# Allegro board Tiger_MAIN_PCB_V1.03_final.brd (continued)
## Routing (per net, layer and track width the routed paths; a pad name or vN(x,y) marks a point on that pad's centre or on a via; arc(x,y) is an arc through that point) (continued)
M_B_DQS_DN*<5>: length 60.5
  TOP w0.076: U1.AY26 200.58,56.26 200.56,56.24 200.5,56.24 200.37,56.19 200.37,56.19 200.29,56.05 200.24,55.94 200.24,55.66 200.28,55.58 200.28,55.37 200.23,55.26 200.23,55.04 200.28,54.93 200.28,54.64 200.07,54.42 200.07,53.21 199.87,53.01 199.87,48.48 199.38,48 199.18,48 198.95,48.24 v2(198.95,48.33)
  TOP w0.114: CN1.74 221.11,14.92 220.97,15.07 220.97,15.72 221.15,15.9 221.47,15.9 v2(221.62,15.75)
  LAY3 w0.076: v2(198.95,48.33) 199.12,48.15 199.33,48.15 199.57,47.92 199.57,45.5 198.12,44.05 198.12,44.03 198.08,44 198.08,43.99 198.08,43.98 198.08,43.98 198.07,43.98
  LAY3 w0.094: v2(221.62,15.75) 221.81,15.94 222.1,15.94 222.32,16.16 222.32,17.19 220.64,18.87 220.64,20.91 218.68,22.87 212.46,22.87 211.77,23.56 211.77,23.57 211.77,23.57 197.68,37.65 197.68,43.59 198.07,43.98 198.07,43.98
M_B_DQS_DN*<6>: length 56.8
  TOP w0.076: U1.AR25 v2(201.53,58.88)
  TOP w0.114: v2(181.87,19.45) 182,19.59 182.44,19.59 182.72,19.87 182.72,21.85 CN1.219
  LAY6 w0.076: 197.93,51 201.04,54.1 201.04,55.09 202.21,56.27 202.21,56.94 201.91,57.24 201.91,58.5 v2(201.53,58.88)
  LAY6 w0.094: 197.93,51 197.93,46.09 195.49,43.65 188.16,36.32 188.14,36.32 182.89,31.07 182.89,29.91 182.81,29.83 182.26,29.83 182.05,29.62 182.05,29.27 182.26,29.06 182.79,29.06 182.89,28.96 182.89,28.77 182.81,28.69 182.26,28.69 182.05,28.48 182.05,28.13 182.26,27.92 182.79,27.92 182.89,27.81 182.89,27.63 182.81,27.54 182.26,27.54 182.05,27.34 182.05,26.99 182.26,26.78 182.79,26.78 182.89,26.67 182.89,25.85 181.34,24.3 181.34,23.46 181.36,23.44 181.36,22.91 181.14,22.69 181.14,19.82 181.36,19.59 181.72,19.59 v2(181.87,19.45)
M_B_DQS_DN*<7>: length 56.3
  TOP w0.076: U1.AR22 v2(199.7,58.88)
  TOP w0.114: CN1.240 177.61,15.58 v2(177.7,15.67)
  LAY6 w0.076: v2(199.7,58.88) 199.33,58.51 199.33,57.23 199.04,56.94 199.04,55.78 197.62,54.36 197.62,54.21 196.71,53.3 196.12,53.3 193.68,50.86 193.68,48.35 182.95,37.62 182.95,36.99 182.18,36.21 182.18,36.19 182.16,36.18
  LAY6 w0.094: v2(177.7,15.67) 177.46,15.91 177.46,23.41 177.5,23.45 177.5,24.83 177.29,25.04 177.17,25.04 177.07,25.13 177.07,25.32 177.17,25.41 177.29,25.41 177.5,25.62 177.5,25.97 177.29,26.18 177.17,26.18 177.07,26.27 177.07,26.46 177.17,26.55 177.29,26.55 177.5,26.76 177.5,31.51 181.8,35.82 181.8,35.82 182.16,36.18
M_B_DQS_DP<0>: length 59.5
  TOP w0.076: U1.AY38 208.32,56.19 208.4,56.05 208.44,55.94 208.44,55.66 208.41,55.58 208.41,55.37 208.46,55.26 208.46,55.24 208.46,55.07 208.46,55.04 208.41,54.93 208.41,54.54 208.54,54.41 208.54,53.92 208.36,53.74 208.36,52.73 208.53,52.57 208.53,50.17 208.29,49.93 208.03,49.93 207.97,49.87 v2(207.97,49.63)
  TOP w0.114: v2(235.86,20.03) 236.01,19.89 236.35,19.89 236.54,20.07 236.54,20.9 236.37,21.07 CN1.13
  LAY3 w0.094: v2(207.97,49.63) 207.97,49.79 207.82,49.94 207.53,49.94 207.38,49.8 207.38,48.75 207.57,48.56 207.57,46 207.58,45.99 207.61,46.12 207.61,45.96 207.61,45.96 207.61,45.79 207.62,45.78 207.62,45.14 216.16,36.6 223.02,36.6 223.3,36.32 223.32,36.32 224.36,35.28 235.17,24.47 235.17,23.46 235.15,23.44 235.15,23.21 235.25,23.11 235.5,23.11 235.7,22.91 235.7,22.57 235.5,22.37 235.25,22.37 235.15,22.28 235.15,22.09 235.25,21.99 235.47,21.99 235.67,21.79 235.67,21.45 235.47,21.25 235.25,21.25 235.15,21.16 235.15,19.87 235.4,19.63 235.5,19.63 235.6,19.72 235.6,19.97 235.66,20.03 v2(235.86,20.03)
M_B_DQS_DP<1>: length 60.9
  TOP w0.076: v2(204.41,47.68) 204.67,47.94 204.99,47.94 205.3,48.24 205.3,53.72 205.43,53.85 205.43,54.97 205.37,55.08 205.37,55.09 205.37,55.2 205.43,55.33 205.43,55.61 205.39,55.69 205.39,55.91 205.42,55.97 205.47,56.05 205.51,56.07 205.6,56.07 205.66,56.01 205.66,55.8 U1.BA34
  TOP w0.114: v2(230.61,15.75) 230.82,15.96 231.04,15.96 231.26,15.75 231.26,15.06 231.11,14.92 CN1.34
  LAY3 w0.076: 204.36,43.88 204.36,44.9 204.86,45.4 204.86,47.85 204.73,47.98 204.54,47.98 204.41,47.85 v2(204.41,47.68)
  LAY3 w0.094: 204.36,43.88 204.36,42.1 210.18,36.27 210.18,36.25 214.73,31.71 221.93,31.71 229.98,23.65 229.98,23.44 230,23.43 230,19.29 229.75,19.05 229.75,16.19 229.98,15.96 230.4,15.96 v2(230.61,15.75)
M_B_DQS_DP<2>: length 52.8
  TOP w0.076: U1.AR38 v2(208.85,58.88)
  TOP w0.114: v2(192.78,20.19) 192.86,20.28 CN1.179
  LAY6 w0.076: v2(208.85,58.88) 208.83,58.88 208.32,58.37 208.32,57.12 208.35,57.09 208.35,53.98 206.82,52.46 206.82,52.45 206.83,52.44
  LAY6 w0.094: v2(192.78,20.19) 192.78,23.43 192.77,23.44 192.77,24.77 192.98,24.97 193.34,24.97 193.43,25.07 193.43,25.26 193.34,25.35 192.98,25.35 192.77,25.56 192.77,25.91 192.98,26.12 193.34,26.12 193.43,26.21 193.43,26.4 193.34,26.49 192.98,26.49 192.77,26.7 192.77,27.05 192.98,27.26 193.34,27.26 193.43,27.35 193.43,27.54 193.34,27.64 192.98,27.64 192.77,27.85 192.77,28.55 193.39,29.17 193.69,29.17 193.78,29.08 193.91,29.08 194.04,29.21 194.04,29.34 193.95,29.44 193.95,29.73 194.2,29.98 194.5,29.98 194.59,29.89 194.72,29.89 194.85,30.02 194.85,30.15 194.76,30.25 194.76,30.54 195.01,30.79 195.31,30.79 195.4,30.7 195.53,30.7 195.66,30.83 195.66,30.96 195.57,31.06 195.57,31.35 195.82,31.6 196.11,31.6 196.24,31.47 196.34,31.47 196.47,31.6 196.47,31.77 196.38,31.86 196.38,32.16 198.81,34.59 198.81,36.24 206.83,44.26 206.83,52.44
M_B_DQS_DP<3>: length 55
  TOP w0.076: U1.AR32 v2(205.19,58.88)
  TOP w0.114: v2(187.11,15.75) 187.22,15.86 187.24,15.86 187.26,15.88 187.61,15.88 187.75,15.74 187.75,13.93 CN1.200
  LAY6 w0.076: 203.12,46.62 203.12,46.63 203.11,46.64 203.11,46.69 203.1,46.7 203.1,52.45 203.94,53.29 203.94,54.45 205.15,55.65 205.15,56.67 205.74,57.26 205.74,58.48 205.33,58.88 v2(205.19,58.88)
  LAY6 w0.094: 203.12,46.62 203.12,45.08 198.93,40.88 198.38,40.88 193.55,36.06 193.55,36.04 188.72,31.2 188.72,24.98 188.73,24.97 188.73,23.79 188.72,23.78 188.72,23.44 188.71,23.43 188.71,17.12 187.56,15.98 187.34,15.98 v2(187.11,15.75)
M_B_DQS_DP<4>: length 58.8
  TOP w0.076: U1.AY30 203.33,56.19 203.42,56.05 203.46,55.94 203.46,55.66 203.43,55.58 203.43,55.37 203.48,55.26 203.48,55.04 203.43,54.93 203.43,54.32 203.46,54.29 203.46,53.89 203.46,53.89 203.46,53.75 203.09,53.38 203.09,50.26 202.9,50.07 202.82,50.07 202.53,49.78 v2(202.53,49.63)
  TOP w0.114: CN1.55 225.86,21.11 226.11,20.86 226.11,20.03 225.91,19.84 225.56,19.84 v2(225.37,20.03)
  LAY3 w0.076: v2(202.53,49.63) 202.42,49.63 202.28,49.77 202.28,49.96 202.2,50.03 202,50.03 201.88,49.92 201.88,46.16 202.08,45.96 202.08,45.83 202.08,45.26 201.12,44.3 201.12,43.87 201.14,43.85 201.14,43.8 201.15,43.79 201.15,43.78
  LAY3 w0.094: v2(225.37,20.03) 224.96,19.63 224.84,19.63 224.7,19.77 224.7,23.7 224.47,23.93 224.47,23.94 220.19,28.23 214.93,28.23 214.72,28.02 214.72,27.74 214.62,27.65 214.43,27.65 214.34,27.74 214.34,28.02 214.13,28.23 213.78,28.23 213.57,28.02 213.57,27.74 213.48,27.65 213.29,27.65 213.2,27.74 213.2,28.02 212.99,28.23 212.37,28.23 204.29,36.31 204.28,36.31 201.15,39.43 201.15,43.78
M_B_DQS_DP<5>: length 60.5
  TOP w0.076: U1.BA26 200.68,55.8 200.68,56.01 200.61,56.07 200.53,56.07 200.49,56.05 200.44,55.97 200.41,55.91 200.41,55.69 200.45,55.61 200.45,55.33 200.39,55.2 200.39,55.1 200.45,54.96 200.45,54.57 200.23,54.35 200.23,53.15 200.03,52.94 200.03,48.41 199.45,47.84 199.11,47.84 v2(198.95,47.68)
  TOP w0.114: CN1.76 220.62,14.92 220.76,15.07 220.76,15.8 221.06,16.1 221.38,16.1 v2(221.62,16.33)
  LAY3 w0.076: 197.94,44.11 199.4,45.57 199.4,47.85 199.26,47.99 199.07,47.99 198.95,47.87 v2(198.95,47.68)
  LAY3 w0.094: v2(221.62,16.33) 221.82,16.13 222.02,16.13 222.14,16.24 222.14,17.12 220.45,18.8 220.45,20.83 218.6,22.69 212.39,22.69 211.77,23.3 211.75,23.3 211.63,23.43 211.63,23.43 199.03,36.03 199.03,36.05 197.5,37.58 197.5,43.66 197.94,44.11
M_B_DQS_DP<6>: length 56.8
  TOP w0.076: U1.AR27 v2(202.45,58.88)
  TOP w0.114: CN1.221 182.5,21.86 182.5,19.97 182.34,19.81 182.09,19.81 v2(181.87,20.03)
  LAY6 w0.076: v2(202.45,58.88) 202.45,59.05 202.38,59.11 202.15,59.11 202.08,59.04 202.08,57.31 202.38,57 202.38,56.2 201.21,55.03 201.21,54.04 198.12,50.95 198.12,50.94
  LAY6 w0.094: 198.12,50.94 198.12,46.02 183.09,30.99 183.09,29.83 182.89,29.63 182.34,29.63 182.24,29.54 182.24,29.35 182.34,29.26 182.87,29.26 183.09,29.04 183.09,28.69 182.89,28.49 182.34,28.49 182.24,28.4 182.24,28.21 182.34,28.12 182.87,28.12 183.09,27.89 183.09,27.54 182.89,27.35 182.34,27.35 182.24,27.25 182.24,27.07 182.34,26.97 182.87,26.97 183.09,26.75 183.09,25.77 181.54,24.22 181.54,22.84 181.32,22.62 181.32,19.9 181.44,19.78 181.61,19.78 v2(181.87,20.03)
M_B_DQS_DP<7>: length 56.4
  TOP w0.076: U1.AR21 v2(198.79,58.88)
  TOP w0.114: CN1.242 177.11,15.58 v2(177.03,15.67)
  LAY6 w0.076: v2(198.79,58.88) 199.17,58.5 199.17,57.3 198.87,57.01 198.87,55.85 197.45,54.43 197.45,54.28 196.64,53.46 196.05,53.46 193.52,50.93 193.52,48.42 182.78,37.69 182.78,37.05 182.06,36.33 182.04,36.33 182.02,36.32
  LAY6 w0.094: 182.02,36.32 177.3,31.59 177.3,26.84 177.21,26.75 177.09,26.75 176.88,26.54 176.88,26.19 177.09,25.98 177.21,25.98 177.3,25.89 177.3,25.7 177.21,25.61 177.09,25.61 176.88,25.4 176.88,25.05 177.09,24.84 177.21,24.84 177.3,24.75 177.3,23.51 177.27,23.49 177.27,15.91 v2(177.03,15.67)
M_B_ODT<0>: length 54
  TOP w0.076: U1.BA42 209.95,55.33 209.81,55.18 209.81,55.18 209.8,55.18 209.68,54.93 209.68,54.6 209.75,54.54 209.75,53.74 209.89,53.6 209.89,53.38 210.01,53.25 210.01,51.38 210.42,50.97 v2(210.42,50.8)
  TOP w0.153: v2(197.89,18.87) 198.03,18.73 198.66,18.73 198.86,18.93 CN1.155
  LAY6 w0.076: 209.45,44.29 209.38,44.35 209.38,50.96 209.78,51.37 210.03,51.37 210.42,50.97 v2(210.42,50.8)
  LAY6 w0.137: v2(197.89,18.87) 197.58,18.87 197.42,19.03 197.42,21.61 197.55,21.75 197.92,21.75 198.06,21.89 198.06,22.16 197.92,22.3 197.55,22.3 197.42,22.44 197.42,22.71 197.55,22.85 197.92,22.85 198.06,22.99 198.06,23.26 197.92,23.4 197.55,23.4 197.42,23.54 197.42,24.01 196.91,24.52 196.91,24.8 197.04,24.93 197.48,24.93 197.62,25.07 197.62,25.34 197.47,25.49 196.93,25.49 196.79,25.63 196.79,25.91 196.93,26.04 197.53,26.04 197.66,26.17 197.66,26.44 197.52,26.58 197.04,26.58 196.91,26.72 196.91,27.09 197.15,27.33 197.35,27.33 197.59,27.08 197.76,27.08 197.91,27.24 197.91,27.45 197.69,27.67 197.69,27.87 202.67,32.85 202.67,36.04 209.45,42.82 209.45,44.29
M_B_ODT<1>: length 55.1
  TOP w0.076: U1.AW42 210.18,56.54 210.18,56.32 210.22,56.28 210.22,55.97 210.18,55.93 210.18,55.66 210.22,55.58 210.22,55.37 210.16,55.26 210.16,55.03 210.18,55.01 210.22,54.93 210.22,54.73 210.22,54.72 210.22,54.64 210.08,54.51 210.08,53.88 210.22,53.74 210.22,53.53 210.58,53.16 v2(210.58,52.95)
  TOP w0.153: CN1.161 197.36,17.7 197.06,17.39 195.69,17.39 195.32,17.76 195.32,18.42 195.53,18.64 196.24,18.64 v2(196.4,18.48)
  LAY6 w0.076: v2(210.58,52.95) 210.37,52.95 208.89,51.48 208.89,45.76 208.5,45.36
  LAY6 w0.137: 208.5,45.36 208.5,43.07 201.73,36.3 201.73,33.18 195.67,27.12 195.67,23.76 195.81,23.62 196.31,23.62 196.45,23.49 196.45,23.21 196.32,23.09 195.97,23.09 195.85,22.97 195.85,18.62 196,18.48 v2(196.4,18.48)
M_B_RAS_N: length 54.8
  TOP w0.076: v2(212,50.03) 211.81,50.22 211.81,53.06 211.81,53.55 211.71,53.65 211.71,55.46 211.47,55.7 211.47,56.17 211.45,56.24 211.34,56.45 211.18,56.61 U1.AW44
  TOP w0.153: v2(199.62,15.14) CN1.152
  LAY6 w0.076: v2(212,50.03) 211.43,50.03 211.18,49.78 211.18,44.8 211.52,44.46
  LAY6 w0.137: v2(199.62,15.14) 199.57,15.18 198.56,15.18 198.29,14.92 198.29,14.23 198.49,14.03 198.84,14.03 198.96,14.15 198.96,14.45 199.1,14.59 199.37,14.59 199.51,14.45 199.51,14.17 199.66,14.02 200.08,14.02 200.43,14.36 200.43,26.96 205.19,31.73 205.19,35.22 211.52,41.55 211.52,44.46
M_B_WE_N: length 55.9
  TOP w0.076: U1.AY44 211.18,55.88 211.08,55.78 211.08,55.77 211,55.55 211,55.42 211.07,55.19 211.07,55.05 211.01,54.93 211.01,54.66 211.21,54.46 211.21,53.69 211.21,53.41 211.31,53.31 211.31,52.85 211.31,51.51 211.21,51.4 211.21,51.03
  TOP w0.102: 211.21,51.03 211.21,48.23 211.61,47.82 211.61,44.32 211.04,43.75 209.4,43.75 209.06,44.09 209.06,44.8 209.16,44.9 209.66,44.9 209.76,45 209.76,45.21 209.66,45.31 209.16,45.31 209.06,45.41 209.06,45.61 209.16,45.72 209.66,45.72 209.76,45.82 209.76,46.02 209.66,46.12 209.16,46.12 209.06,46.22 209.06,46.43 209.53,46.9 v2(210.42,46.9)
  TOP w0.153: CN1.151 199.86,20.53 v2(199.36,20.03)
  LAY6 w0.076: v2(210.42,46.9) 210.14,46.9 210.01,46.77 210.01,44.66 210.49,44.18
  LAY6 w0.137: 210.49,44.18 210.49,42.52 203.8,35.84 203.8,32.46 198.93,27.58 198.93,20.47 v2(199.36,20.03)
MDI0+: length 12.2
  TOP w0.097: v2(116.03,32.23) 115.15,32.23 U11.2
  BOTTOM w0.097: U9.1 122.88,38.32 122.23,38.32 121.84,37.93 120.4,37.93 119.33,36.86 119.33,34.09 117.61,32.36 116.16,32.36 v2(116.03,32.23)
MDI0-: length 12.2
  TOP w0.097: v2(116.03,32.84) 115.14,32.84 U11.3
  BOTTOM w0.097: v2(116.03,32.84) 116.16,32.71 117.46,32.71 118.99,34.23 118.99,37 120.26,38.27 121.7,38.27 122.09,38.66 122.86,38.66 U9.2
MDI1+: length 11.1
  TOP w0.097: v2(116.03,35.2) 115.15,35.2 U11.5
  BOTTOM w0.097: v2(116.03,35.2) 116.37,35.2 116.5,35.33 117.51,35.33 118.36,36.18 118.36,38.4 119.36,39.4 121.59,39.4 121.72,39.53 122.86,39.53 U9.4
MDI1-: length 11.1
  TOP w0.097: v2(116.03,35.81) 115.14,35.81 U11.6
  BOTTOM w0.097: v2(116.03,35.81) 116.37,35.81 116.5,35.68 117.37,35.68 118.01,36.32 118.01,38.54 119.22,39.75 121.45,39.75 121.57,39.87 122.88,39.87 U9.5
MDI2+: length 9.5
  TOP w0.097: v2(116.03,38.17) 115.15,38.17 U11.8
  BOTTOM w0.097: U9.7 122.87,40.72 121.61,40.72 121.5,40.83 118.72,40.83 117.26,39.38 117.26,38.79 116.8,38.32 116.18,38.32 v2(116.03,38.17)
MDI2-: length 9.5
  TOP w0.097: U11.9 115.15,38.78 v2(116.03,38.78)
  BOTTOM w0.097: U9.8 122.87,41.07 121.75,41.07 121.65,41.17 118.58,41.17 116.92,39.52 116.92,38.93 116.65,38.67 116.14,38.67 v2(116.03,38.78)
MDI3+: length 9.2
  TOP w0.097: U11.11 115.14,41.14 v2(116.03,41.14)
  BOTTOM w0.097: U9.10 122.84,41.95 122.28,41.95 121.25,42.98 121.25,42.98 119.22,42.98 117.48,41.25 116.14,41.25 116.04,41.14 v2(116.03,41.14)
MDI3-: length 9.2
  TOP w0.097: v2(116.03,41.75) 115.15,41.75 U11.12
  BOTTOM w0.097: v2(116.03,41.75) 116.19,41.59 117.34,41.59 119.08,43.33 121.28,43.33 121.28,43.32 121.4,43.32 122.42,42.3 U9.11
ME_FLASH: length 179.9
  TOP w0.102: v2(111.31,60.71) 113.84,58.18 126.05,58.18 141.77,42.46 141.77,39.01 151.82,28.96 164.47,28.96 166.34,27.09 168.45,27.09 170.43,25.11 180.73,25.11 193.11,37.49 195.13,37.49 196.59,38.95 R795.2
  LAY6 w0.102: v2(111.31,60.71) 111.21,60.61 97.07,60.61 96.32,61.36 69.69,61.36 67.91,63.14 66.41,63.14 62.5,67.05 45.71,67.05 v2(45.41,67.36)
  BOTTOM w0.102: U22.89 45.51,67.46 v2(45.41,67.36) R400.2
MIC1L-VREFO: length 10.6
  LAY6 w0.203: v2(10.32,18.91) 11.05,18.18 11.05,14.66 v2(13.95,11.77)
  BOTTOM w0.203: U16.31 10.56,19.16 v2(10.32,18.91) ; R355.2 v2(13.95,11.77)
MIC1R-VREFO: length 12.6
  LAY6 w0.203: v2(10.41,10.05) 10.41,12.31 9.53,13.19 9.53,17.96 v2(10.01,18.44)
  BOTTOM w0.203: R356.2 10.41,11.18 v2(10.41,10.05) ; U16.30 10.83,18.76 10.52,18.44 v2(10.01,18.44)
MIC2-VREFO: length 11.1
  LAY6 w0.203: v2(10.24,17.94) 10.62,17.55 10.62,14.36 v2(14.03,10.96)
  BOTTOM w0.203: v2(14.03,10.96) 14.59,11.52 R3119.1 ; v2(10.24,17.94) 10.46,17.94 10.88,18.36 U16.29
MIC_SEL_DET: length 81.6
  TOP w0.305: v2(19.76,11.2) 33.6,11.2 35.04,12.64 J2.6
  LAY3 w0.102: v2(19.76,11.2) 20.27,11.72 21.27,11.72 22.07,12.52 22.07,20.54 25.65,24.13 25.65,30.41 43.64,48.41 43.64,59.22 v2(42.87,59.99)
  BOTTOM w0.102: R359.1 17.5,12.73 18.36,11.87 Q36.1 v2(19.76,11.2) ; R104.1 v2(42.87,59.99)
MIC_SEL_SPDIF: length 106.8
  LAY3 w0.102: v2(52.01,75.37) 52.58,74.8 52.58,60.83 52.08,60.32 52.08,59.22 52.58,58.71 52.58,35.06 v2(43.16,25.64) ; v2(17.26,24.75) 17.05,24.53 v2(17.05,12.42)
  LAY6 w0.102: v2(17.26,24.75) 17.26,25.28 21.6,29.62 21.6,30.96 23.2,32.56 36.24,32.56 v2(43.16,25.64)
  BOTTOM w0.102: R3122.1 v2(52.01,75.37) ; v2(17.05,12.42) 17.05,12.33 16.4,11.68 R346.2 16.42,10.92 Q36.3 ; v2(17.26,24.75) 17.15,24.63 17.15,22.52 16.73,22.1 U16.48
MPHY_EXT_PWR_GATE*: length 27.3
  TOP w0.076: U1.AM10 192.34,60.78 v2(192.39,60.78)
  LAY3 w0.076: v2(192.39,60.78) 192.24,60.78 191.98,60.52 191.98,57.54 191.65,57.21 190.9,57.21 190.7,57.41 187.85,57.41 187.02,56.58 182.54,56.58 179.51,53.55 176.13,53.55
  LAY3 w0.087: v2(172.97,51.43) 175.09,53.55 176.13,53.55
  BOTTOM w0.109: R54.2 171.94,51.08 172.29,51.43 v2(172.97,51.43)
Net_51: length 0.6
  TOP w0.076: 193.16,70.54 193.16,70.43 v2(192.81,70.08)
NOA_RCOMP: length 12.4
  TOP w0.254: v2(225.94,82.65) 225.96,82.65 226.39,83.08 226.39,83.99 R130.1 ; v2(220.73,74.95) 220.66,74.92 U1.E60
  LAY3 w0.254: v2(220.73,74.95) 220.73,75.87 223.65,78.79 224.47,78.79 225.94,80.26 v2(225.94,82.65)
OVERT: length 4.7
  BOTTOM w0.109: R506.1 57.53,75.77 57.53,73.39 56.72,72.58 U22.119
OVPA: length 31.8
  TOP w0.305: v2(121.66,84.39) 121.3,84.74 U2529.7
  BOTTOM w0.305: 106.91,96.9 106.91,97.52 107.68,98.29 120.06,98.29 123.34,95.02 123.34,85.72 122,84.39 v2(121.66,84.39)
PCH_EDM: length 7.9
  TOP w0.076: R718.2 182.13,52.12 184.24,54.24 184.98,54.24 186.37,55.62 186.73,55.62 186.92,55.81 187.51,55.81 U1.AY3
PCH_LPC_CLK1: length 155.6
  TOP w0.076: 183.66,46.49 184.04,46.49 186.67,49.12 186.67,51.95 187.17,52.45 187.65,52.45 188.92,53.72 190.95,53.72 191.49,54.26 191.49,54.45 191.69,54.65 191.69,54.93 191.64,55.05 191.64,55.19 191.7,55.42 191.7,55.54 191.63,55.74 191.53,55.86 191.43,55.97 U1.AY9
  TOP w0.102: 183.66,46.49 181.4,44.23 181.4,37.88 179.7,36.18
  TOP w0.109: 179.7,36.18 178.99,35.47 168.8,35.47 167.13,33.8 153.81,33.8 146.32,41.29 146.32,44.34 127.93,62.72 118.15,62.72 110.47,70.4 87.19,70.4 85.03,68.25 73.17,68.25 71.38,66.45 CN16.10
PCH_PLT_RST*: length 30.9
  TOP w0.076: U1.AN10 191.99,60.54 v2(192.39,60.15)
  TOP w0.109: U2.2 168.09,51.36 168.22,51.23 168.59,51.23 168.74,51.38 U2.1 169.76,51.89 171.06,53.18 v2(171.06,53.32)
  LAY6 w0.087: v2(171.06,53.32) 171.11,53.27 181.07,53.27 183.83,56.03 190.54,56.03 191.93,57.41 191.93,59.69 v2(192.39,60.15)
PCH_POPIRCOMP: length 20.6
  TOP w0.254: U1.AU16 v2(196.05,57.61)
  TOP w0.305: R42.1 v2(182.06,49.07)
  LAY6 w0.203: 194.51,55.84 196.05,57.38 v2(196.05,57.61)
  LAY6 w0.254: 194.51,55.84 191.05,52.38 189.57,52.38
  LAY6 w0.305: 189.57,52.38 187.97,52.38 187.28,53.07 184.48,53.07 181.7,50.3 181.7,49.42 v2(182.06,49.07)
PCH_PWROK: length 424.2
  TOP w0.076: U1.BA20 197.76,55.21 197.76,54.28 196.92,53.44 196.92,52.07 194.46,49.6 194.46,48.93 v2(194.09,48.56)
  LAY3 w0.087: v2(52.67,93.28) 52.19,92.79 52.19,80.73 51.22,79.76 v2(51.22,75.46)
  LAY6 w0.076: 176.99,37.52 178.62,37.52 180.79,39.7 180.79,40.15 v2(180.87,40.23)
  LAY6 w0.087: 176.99,37.52 171.73,32.27 171.73,24.84 169.87,22.97 169.87,16.89 173.53,13.22 196.79,13.22 198.71,11.3 228.22,11.3 229.81,12.89 229.81,27.67 234.35,32.2 234.35,49.6 238.83,54.08 238.83,68.12 238.42,68.52 238.42,82.04 236.68,83.78 236.68,85.01 v2(236.14,85.56) 236.02,85.44 232.52,85.44 231.92,84.84 229.47,84.84 226.29,81.65 224.99,81.65 222.87,79.53 219.67,79.53 218.77,80.43 218.77,84.43 216.13,87.08 209.65,87.08 207.08,89.64 206.07,89.64 200.31,95.41 192.26,95.41 189.69,92.83 181.76,92.83 180.77,93.81 172.15,93.81 169.87,96.1 150.85,96.1 142,87.24 135.79,87.24 134.5,88.54 131.67,88.54 129.1,91.12 121.19,91.12 118.86,88.78 113.28,88.78 111.91,90.15 86.33,90.15 83.62,92.86 53.09,92.86 v2(52.67,93.28)
  BOTTOM w0.076: v2(194.09,48.56) 194.13,48.52 R16.2 194.77,44.56
  BOTTOM w0.102: v2(180.87,40.23) 181.35,40.71 191.72,40.71 194.77,43.76 194.77,44.56
  BOTTOM w0.109: v2(236.14,85.56) 236.57,85.99 U103.39 ; v2(51.22,75.46) 51.22,75.45 R417.2
PCH_SLP_LAN*: length 7.4
  TOP w0.076: U1.AW15 195.12,56.63 194.96,56.47 194.96,56.47 194.81,56.14 194.81,54.67 194.92,54.56 194.92,54.17 192.17,51.42 191.73,51.42 TP10.1
PCH_SLP_S5*: length 7.9
  TOP w0.076: U1.AY16 195.7,56.26 196,55.95 196,55.53 195.84,55.36 195.84,53.65 192.64,50.45 TP8.1
PCH_SLP_SA*: length 17.4
  TOP w0.076: U1.AN16 v2(196.05,60.15)
  LAY3 w0.076: v2(196.05,60.15) 195.5,59.6 195.5,57.26
  LAY3 w0.102: 195.5,57.26 195.05,56.82 194.12,56.82 192.63,55.33 189.14,55.33 187.92,54.11 183.08,54.11 v2(183.07,54.11)
PCH_SLP_WLAN*: length 7.2
  TOP w0.076: TP11.1 193.3,49.3 193.3,50.61 196.17,53.47 196.17,54.72 U1.BB17
PCH_SUSACK*: length 159.1
  TOP w0.076: U1.AP11 193.22,59.51 v2(193.3,59.51)
  TOP w0.109: R554.2 R555.1 49.36,58.76 v2(49.96,59.36)
  LAY6 w0.076: v2(193.3,59.51) 192.93,59.14 192.93,57.63 191.11,55.81 183.96,55.81 181.22,53.07 176.48,53.07 v2(176.18,52.76) 176.13,52.76
  LAY6 w0.087: 176.13,52.76 170.64,52.76 169.86,53.55 163.15,53.55 162.1,52.5 159.36,52.5 157.69,54.17 156.66,54.17 154.09,51.61 147.24,51.61 145.78,53.07 119.35,53.07 114.38,58.04 102.18,58.04 101.06,59.16 96.36,59.16 95.6,59.93 71.7,59.93 71.09,59.32 68.26,59.32 68.15,59.42 64.64,59.42 64.09,58.87 54.08,58.87 53.03,59.93 50.53,59.93 v2(49.96,59.36)
  BOTTOM w0.076: 176.13,52.76 v2(176.18,52.76)
  BOTTOM w0.109: 176.13,52.76 175.72,52.76 175.52,52.56 R25.1 R21.2
PCH_SUSACK_R*: length 1.9
  TOP w0.102: v2(47.56,58.91) 47.57,58.9 47.57,58.16 R554.1
  BOTTOM w0.109: U22.68 47.41,59.06 v2(47.56,58.91)
PCH_SUSPWRACK*: length 21.7
  TOP w0.076: U1.AR13 193.85,59.24 v2(194.22,58.88)
  LAY3 w0.076: v2(194.22,58.88) 193.85,58.51 193.85,57.87 192.18,56.2 188.04,56.2
  LAY3 w0.102: 188.04,56.2 187.87,56.03 183.24,56.03 180.08,52.87 177.08,52.87 v2(176.84,52.62)
  BOTTOM w0.102: v2(176.84,52.62) 176.84,52.44 R25.2
PCH_SYSRST*: length 148.5
  TOP w0.102: R633.1 183.16,77.35 R14.2 182.81,76.14 181.87,76.14 181.4,76.61 181.4,77.99 179.71,79.68 177.13,79.68 175.63,78.18 174.54,78.18 172.19,75.83 v2(172.19,75.47)
  LAY3 w0.102: v2(60.1,85.44) 58.37,83.71 58.37,75.31 v2(58.33,75.26)
  LAY6 w0.102: v2(172.19,75.47) 171.63,76.03 165.51,76.03 164.22,74.74 151.91,74.74 149.6,72.42 138.78,72.42 137.61,71.26 125.05,71.26 121.75,74.56 111.22,74.56 110.51,73.85 95.74,73.85 84.16,85.43 60.11,85.43 v2(60.1,85.44)
  BOTTOM w0.102: R413.2 v2(58.33,75.26)
PCIE_RCOMPN: length 6.1
  TOP w0.102: 186.02,75.54 186.16,75.54 186.22,75.48 186.68,75.48 186.77,75.57 187.21,75.57 187.34,75.44 187.63,75.44 187.72,75.53 187.9,75.53 188.51,74.92 188.61,74.92 188.8,74.74 188.8,74.47 U1.F5
  TOP w0.109: R67.2 186.02,75.54
PCIE_RCOMPP: length 6.4
  TOP w0.089: 185.96,76.14 186.66,76.14 186.84,75.97
  TOP w0.102: 186.84,75.97 187.25,75.97 187.4,76.13 188.29,76.13 188.46,75.97 188.46,75.37 188.79,75.03 188.88,75.03 U1.E5
  TOP w0.109: 185.96,76.14 185.2,76.14 184.85,76.49 R67.1
PCIE_RST: length 103.4
  TOP w0.076: U1.AB11 192.51,66.15 v2(192.17,65.81)
  LAY6 w0.102: v2(192.17,65.81) 192.17,64.37 191.15,63.34 191.15,62.66 190.72,62.23 187.15,62.23 185.9,60.97 182.35,60.97 181.74,60.36 174.76,60.36 174.05,61.07 173.08,61.07 171.34,59.33 168.52,59.33 167.19,60.66 162.69,60.66 161.7,59.67 156.74,59.67 152.42,55.35 147.96,55.35 147.16,56.16 135.67,56.16 v2(135.45,56.37)
  BOTTOM w0.102: U18.2 137.41,24.52 137.61,24.32 138.49,24.32 139.34,25.17 139.34,28.43 142.23,31.33 142.23,39.52 137.28,44.47 137.28,54.54 v2(135.45,56.37)
PCIE_RX_DN*<4>: length 101.6
  TOP w0.076: U1.G18 196.69,73.43 v2(196.96,73.7)
  LAY6 w0.087: v2(131.95,73.36) 131.74,73.57 131.74,73.84 131.92,74.02 133.47,74.02 133.86,73.63 149.01,73.63 151.38,76 160.05,76 161.94,77.9 164.86,77.9 165.32,78.36 166.88,78.36 167.28,77.96 171.63,77.96 172.67,76.92 175.03,76.92 177.11,79 179.88,79 181.03,77.85 186.77,77.85 187.55,77.08 187.56,77.08 187.85,76.78 194.9,76.78 196.43,75.26 196.43,74.19 196.63,73.99 196.74,73.99 196.96,73.77 v2(196.96,73.7)
  BOTTOM w0.109: v2(131.95,73.36) 131.77,73.18 131.77,51.79 132.02,51.53 132.02,48.11 130.13,46.22 130.13,45.7 C394.1
PCIE_RX_DN_1_WIFI: length 130.1
  TOP w0.076: v2(196.05,74.32) 195.81,74.08 U1.F16
  TOP w0.109: v2(128.74,49.2) 128.93,49 128.93,36.31 127.7,35.09 127.7,32.35 128.41,31.64 128.41,25.2 126.93,23.72 125.29,23.72 125.15,23.86 CN26.43
  LAY6 w0.087: v2(196.05,74.32) 195.75,74.61 195.3,74.61 194.5,75.41 193.38,75.41 192.45,76.34 190.57,76.34 189.64,75.41 187.97,75.41 186.93,76.45 186.92,76.45 186.18,77.19 182.36,77.19 181.5,76.32 181.5,75.62 179.68,73.81 179.07,73.81 179.06,73.8 178.99,73.8 178.98,73.81 176.91,73.81 175.34,75.38 173.15,75.38 171.9,76.63 165.4,76.63 164.92,77.12 162.64,77.12 160.78,75.26 151.71,75.26 149.41,72.96 137.73,72.96 137.11,72.34 129.36,72.34 128.94,72.76 128.94,73.35 v2(128.73,73.56)
  BOTTOM w0.109: v2(128.74,49.2) 128.93,49.39 128.93,73.36 v2(128.73,73.56)
PCIE_RX_DN_9_SSD: length 133.3
  TOP w0.076: U1.E22 199.47,74.73 v2(199.74,75)
  TOP w0.109: CN5.5 87.84,52.17 87.98,52.03 93.72,52.03 93.91,52.22 v2(94.25,52.22)
  LAY3 w0.076: 187.22,76.74 189.6,76.74 192.77,79.9 196.33,79.9 196.72,79.52 196.72,77.34 197.96,76.09 197.96,75.26 198.82,74.39 199.87,74.39 200.07,74.6 200.07,74.77 199.84,75 v2(199.74,75) ; 182.14,73.94 180.62,72.42 178.99,72.42 177.34,70.77 176.28,70.77 176.13,70.63
  LAY3 w0.087: v2(94.25,52.22) 94.43,52.04 97.12,52.04 104.2,59.11 129.7,59.11 134.05,63.46 141.14,63.46 144.57,66.9 149.02,66.9 154.48,72.36 159.29,72.36 161.69,69.96 168.16,69.96 169.25,71.05 172.09,71.05 173.35,69.79 175.3,69.79 176.13,70.63 ; 187.22,76.74 187.18,76.74 185.48,75.04 183.24,75.04 182.14,73.94
PCIE_RX_DN_10_SSD: length 137.6
  TOP w0.076: v2(201.46,74.35) 201.34,74.35 U1.F25
  TOP w0.109: CN5.17 87.77,49.17 87.91,49.02 93.11,49.02 v2(93.3,49.21)
  LAY3 w0.076: 180.87,73.94 179.98,73.05 178.66,73.05 177.43,71.81 177.07,71.81 ; 189.9,79.5 189.91,79.5 189.92,79.49 191.23,79.49 192.18,80.44 196.49,80.44 197.35,79.57 197.35,77.66 197.81,77.2 199.58,77.2 201.15,75.63 201.15,74.79 201.14,74.71 v2(201.46,74.35)
  LAY3 w0.087: 177.07,71.81 169.09,71.81 167.89,70.61 162.82,70.61 160.41,73.01 154.22,73.01 148.75,67.55 144.3,67.55 141.18,64.42 133.58,64.42 129.3,60.14 109.04,60.14 108.83,60.35 101.01,60.35 93.51,52.85 93.51,50.68 94.08,50.11 94.08,49.26 93.88,49.06 93.45,49.06 v2(93.3,49.21) ; 180.87,73.94 184.46,77.53 186.48,77.53 186.48,77.53 187.4,77.53 189.37,79.5 189.9,79.5
PCIE_RX_DN_11_SSD: length 140.4
  TOP w0.076: U1.E28 202.7,74.93 v2(202.46,74.93)
  TOP w0.109: v2(91.53,47.79) 91.42,47.67 89.85,47.67 88.2,46.02 87.88,46.02 87.73,46.17 CN5.29
  LAY3 w0.076: 189.9,80.19 189.91,80.19 189.92,80.18 190.7,80.18 191.45,80.93 196.72,80.93 197.83,79.82 197.83,78.09 198.16,77.76 201,77.76 202.42,76.34 202.42,75.71 202.11,75.4 202.09,75.14 202.25,74.95 v2(202.46,74.93)
  LAY3 w0.087: 189.9,80.19 189.09,80.19 188.31,79.42 188.3,79.42 187.23,78.34 182.72,78.34 181.17,76.79 181.17,75.67 179.48,73.99 178.01,73.99 176.64,72.63 164.88,72.63 163.84,73.67 153.4,73.67 147.97,68.23 143.75,68.23 140.73,65.21 133.16,65.21 130.58,62.63 115.23,62.63 114.56,61.96 100.47,61.96 92.72,54.21 92.72,50.27 92.25,49.79 92.25,47.79 92.09,47.63 91.69,47.63 v2(91.53,47.79)
PCIE_RX_DN_12_SSD: length 147.7
  TOP w0.076: v2(203.01,80.48) 203.32,80.16 203.32,80.08 203.63,79.77 203.63,77.97 203.14,77.47 203.14,76.87 203.28,76.73 203.28,75.71 203.25,75.68 203.25,75.42 203.22,75.39 203.22,75.15 203.41,74.96 203.41,74.72 203.56,74.57 203.71,74.57 203.82,74.67 U1.E30
  TOP w0.109: R198.1 89.75,45.53 v2(89.68,45.6)
  LAY3 w0.076: v2(203.01,80.48) 203.01,80.45 202.72,80.16 202.37,80.16 201.73,80.79 199.49,80.79 197.51,82.77 189.92,82.77 189.91,82.78 189.9,82.78
  LAY3 w0.087: v2(89.68,45.6) 89.63,45.6 89.26,45.24 89.26,44.92 89.42,44.76 90.01,44.76 90.42,45.18 90.42,45.94 90.03,46.34 90.03,58.35 98.3,66.62 130.82,66.62 134.83,70.63 147.14,70.63 153.97,77.46 169.9,77.46 173.36,80.92 174.22,80.92 176.18,82.88 182.89,82.88 182.99,82.77 185.37,82.77 185.38,82.78 189.9,82.78
PCIE_RX_DP<4>: length 101.6
  TOP w0.076: v2(196.96,74.32) 196.72,74.08 U1.F18
  LAY6 w0.087: v2(131.35,73.36) 131.56,73.57 131.56,73.92 131.84,74.2 133.55,74.2 133.94,73.81 148.94,73.81 151.31,76.18 159.97,76.18 161.87,78.08 164.79,78.08 165.25,78.54 166.96,78.54 167.35,78.14 171.7,78.14 172.75,77.1 174.95,77.1 177.03,79.18 179.96,79.18 181.1,78.04 186.85,78.04 187.93,76.96 194.98,76.96 196.6,75.33 196.6,74.27 196.7,74.16 196.86,74.16 196.96,74.27 v2(196.96,74.32)
  BOTTOM w0.109: C395.1 129.78,46.17 131.81,48.2 131.81,51.44 131.55,51.7 131.55,73.16 v2(131.35,73.36)
PCIE_RX_DP_1_WIFI: length 130.1
  TOP w0.076: U1.E16 195.82,74.73 v2(196.05,74.95)
  TOP w0.109: v2(129.34,49.2) 129.15,49 129.15,36.22 127.92,35 127.92,32.44 128.63,31.73 128.63,25.11 127.02,23.5 125.3,23.5 125.16,23.36 CN26.41
  LAY6 w0.087: v2(196.05,74.95) 195.88,74.79 195.37,74.79 194.57,75.59 193.45,75.59 192.52,76.51 190.5,76.51 189.57,75.59 188.04,75.59 186.26,77.37 182.29,77.37 181.32,76.4 181.32,75.7 179.6,73.98 179.06,73.98 179.06,73.99 176.99,73.99 175.41,75.57 173.23,75.57 171.98,76.82 165.48,76.82 165,77.3 162.57,77.3 160.7,75.44 151.63,75.44 149.33,73.14 137.65,73.14 137.04,72.53 129.44,72.53 129.13,72.84 129.13,73.35 v2(129.34,73.56)
  BOTTOM w0.109: v2(129.34,49.2) 129.15,49.39 129.15,73.38 v2(129.34,73.56)
PCIE_RX_DP_9_SSD: length 133.3
  TOP w0.076: v2(200.44,75.01) U1.E23
  TOP w0.109: v2(94.25,51.62) 93.91,51.62 93.72,51.81 87.97,51.81 87.82,51.67 CN5.7
  LAY3 w0.076: 185.33,74.86 185.55,74.86 187.27,76.58 189.67,76.58 192.83,79.74 196.26,79.74 196.55,79.45 196.55,77.27 197.8,76.03 197.8,75.19 198.76,74.23 199.93,74.23 200.23,74.53 200.23,74.79 200.44,75 v2(200.44,75.01) ; 182.4,73.94 180.69,72.26 179.06,72.26 177.4,70.61 176.37,70.61 176.13,70.37
  LAY3 w0.087: 182.4,73.94 183.32,74.86 185.33,74.86 ; 176.13,70.37 175.38,69.61 173.27,69.61 172.01,70.87 169.33,70.87 168.23,69.77 161.62,69.77 159.21,72.18 154.56,72.18 149.09,66.71 144.65,66.71 141.22,63.28 134.12,63.28 129.77,58.93 104.27,58.93 97.2,51.86 94.49,51.86 v2(94.25,51.62)
PCIE_RX_DP_10_SSD: length 137.6
  TOP w0.076: U1.E25 200.75,74.4 v2(200.62,74.4)
  TOP w0.109: CN5.19 87.83,48.67 87.96,48.8 93.11,48.8 v2(93.3,48.61)
  LAY3 w0.076: 181,73.81 180.05,72.88 178.73,72.88 177.48,71.63 176.89,71.63 ; v2(200.62,74.4) 200.84,74.39 200.97,74.5 200.98,74.79 200.98,75.56 199.51,77.03 197.74,77.03 197.19,77.59 197.19,79.51 196.42,80.27 192.25,80.27 191.3,79.33 189.92,79.33 189.91,79.32 189.9,79.32
  LAY3 w0.087: v2(93.3,48.61) 93.3,48.64 93.54,48.87 93.95,48.87 94.26,49.18 94.26,50.19 93.69,50.76 93.69,52.77 101.08,60.16 108.76,60.16 108.97,59.95 129.37,59.95 133.66,64.24 141.25,64.24 144.38,67.36 148.82,67.36 154.29,72.83 160.34,72.83 162.74,70.42 167.96,70.42 169.17,71.63 176.89,71.63 ; 181,73.81 184.54,77.35 186.48,77.35 186.48,77.35 187.47,77.35 189.44,79.32 189.9,79.32
PCIE_RX_DP_11_SSD: length 140.4
  TOP w0.076: U1.E27 201.71,75.01 v2(201.52,75.01)
  TOP w0.109: v2(91.53,47.18) 91.53,47.21 91.3,47.45 89.94,47.45 88.29,45.8 87.89,45.8 87.75,45.67 CN5.31
  LAY3 w0.076: v2(201.52,75.01) 201.79,74.99 201.92,75.1 201.95,75.44 201.95,75.47 202.25,75.78 202.25,76.27 200.93,77.59 198.09,77.59 197.67,78.02 197.67,79.75 196.65,80.77 191.52,80.77 190.77,80.02 189.92,80.02 189.91,80.01 189.9,80.01
  LAY3 w0.087: 189.9,80.01 189.16,80.01 188.86,79.71 188.86,79.72 187.3,78.16 182.8,78.16 181.35,76.71 181.35,75.6 179.56,73.81 178.08,73.81 176.72,72.44 164.81,72.44 163.77,73.48 153.48,73.48 148.04,68.05 143.83,68.05 140.8,65.03 133.24,65.03 130.66,62.45 115.31,62.45 114.64,61.78 100.55,61.78 92.91,54.14 92.91,50.19 92.43,49.72 92.43,47.71 92.17,47.45 91.69,47.45 91.53,47.29 v2(91.53,47.18)
PCIE_RX_DP_12_SSD: length 147.7
  TOP w0.076: U1.F30 203.45,74.44 203.24,74.66 203.24,74.89 203.05,75.08 203.05,75.32 202.68,75.7 202.68,76 202.72,76.04 202.72,76.69 202.97,76.94 202.97,77.54 203.47,78.04 203.47,79.7 203.26,79.9 v2(203.01,79.9)
  TOP w0.109: v2(89.08,45.6) 88.96,45.48 R197.1
  LAY3 w0.076: 189.9,82.6 189.91,82.6 189.92,82.61 197.44,82.61 199.42,80.63 201.66,80.63 202.3,79.99 202.92,79.99 v2(203.01,79.9)
  LAY3 w0.087: v2(89.08,45.6) 89.08,44.84 89.34,44.58 90.08,44.58 90.61,45.11 90.61,46.02 90.21,46.41 90.21,58.27 98.38,66.44 130.9,66.44 134.91,70.45 147.22,70.45 154.04,77.28 169.97,77.28 173.44,80.74 174.29,80.74 176.26,82.7 182.81,82.7 182.92,82.59 185.45,82.59 185.45,82.6 189.9,82.6
PCIE_TX_C_DN*<4>: length 7.9
  TOP w0.076: C11.1 197,83.08 197,83.01 197,82.62 197,82.24 197,78.86 197.99,77.87 197.99,76.86 197.77,76.64 197.77,76.36 198.05,76.08 U1.D20
PCIE_TX_C_DN_1_WIFI: length 8.9
  TOP w0.076: C9.1 196.26,82.95 196.26,82.71 196.14,82.59 195.54,82.59 195.45,82.5 195.45,82.26 195.57,82.14 196.12,82.14 196.63,81.63 196.63,78.55 197.23,77.95 197.23,77.4 arc(197.23,77.35) 197.25,77.3 arc(197.26,77.27) 197.27,77.24 arc(197.27,77.24) 197.28,77.23 arc(197.29,77.2) 197.29,77.17 197.29,77.09 arc(197.28,77.03) 197.25,76.97 arc(197.24,76.93) 197.23,76.89 197.23,76.75 arc(197.25,76.66) 197.3,76.58 197.48,76.4 U1.C19
PCIE_TX_C_DP<4>: length 7.9
  TOP w0.076: U1.C20 198.17,76.35 198.31,76.35 198.4,76.45 198.4,76.62 198.15,76.86 198.15,77.94 197.16,78.93 197.16,82.23 197.16,82.55 197.7,83.09 C12.1
PCIE_TX_C_DP_1_WIFI: length 8.8
  TOP w0.076: C10.1 195.28,82.19 195.5,81.97 196.05,81.97 196.47,81.56 196.47,78.48 197.07,77.88 197.07,77.4 arc(197.07,77.33) 197.09,77.26 arc(197.1,77.21) 197.12,77.17 arc(197.12,77.17) 197.12,77.17 197.12,77.09 arc(197.12,77.07) 197.11,77.06 arc(197.11,77.05) 197.1,77.04 arc(197.08,76.97) 197.07,76.89 197.07,76.75 arc(197.1,76.6) 197.19,76.46 197.21,76.44 197.21,75.78 U1.D19
PCIE_TX_DN*<4>: length 118.7
  TOP w0.076: C11.2 197.29,84.35 197.29,84.57 v2(197.09,84.77)
  LAY6 w0.076: v2(197.09,84.77) 197.12,84.74 197.12,84.08 195.89,82.85 190.52,82.85 190.1,83.27 189.9,83.27
  LAY6 w0.087: 189.9,83.27 187.04,83.27 185.61,84.7 177.09,84.7 175.57,83.18 172.14,83.18 171.29,84.03 169.48,84.03 169.25,83.8 163.53,83.8 163.15,84.18 156.69,84.18 153.54,81.03 148.52,81.03 147.94,80.46 145.62,80.46 144.4,79.24 137.53,79.24 137.08,79.68 131.71,79.68 130.19,81.2 126.3,81.2 124.05,78.94 123.75,78.94 v2(123.54,79.15)
  BOTTOM w0.109: U9.18 125.6,43.68 125.42,43.86 125.42,45.86 125.65,46.08 125.65,46.77 125.65,77.54 124.23,78.95 123.74,78.95 v2(123.54,79.15)
PCIE_TX_DN_1_WIFI: length 139.4
  TOP w0.076: C9.2 195.78,84.38 195.78,84.62 v2(196,84.84)
  TOP w0.109: CN26.37 125.15,22.36 125.29,22.22 127.17,22.22 129.33,24.38 129.33,30.74 132.65,34.07 132.65,44.46 130.56,46.56 130.56,49.23 v2(130.32,49.47)
  LAY6 w0.076: 189.9,83.84 190,83.84 190.49,83.35 194.86,83.35 195.69,84.17 195.69,84.53 v2(196,84.84)
  LAY6 w0.087: v2(131.58,80.95) 131.79,81.16 132.69,81.16 133.15,81.63 135.98,81.63 136.7,80.91 139.46,80.91 140.23,80.13 143.62,80.13 145.01,81.52 152.65,81.52 156.08,84.95 165.96,84.95 166.24,84.67 167.82,84.67 168.2,85.05 171.19,85.05 172.59,83.65 175.37,83.65 177.39,85.66 185.61,85.66 187.44,83.84 189.9,83.84
  BOTTOM w0.109: v2(130.32,49.47) 130.7,49.86 130.7,50.73 130.37,51.06 130.37,74.51 132.77,76.91 132.77,80.68 132.15,81.3 131.92,81.3 v2(131.58,80.95)
PCIE_TX_DN_9_SSD: length 2.4
  TOP w0.109: CN5.11 87.84,50.67 87.98,50.53 88.78,50.53 C322.2
PCIE_TX_DN_10_SSD: length 138.7
  TOP w0.076: v2(199.64,81.36) 199.64,80.97 C327.2
  TOP w0.109: CN5.23 88.07,47.67 v2(88.11,47.7)
  LAY3 w0.076: 189.9,83.31 189.91,83.31 189.92,83.32 191.7,83.32 191.94,83.08 197.94,83.08 198.67,82.35 199.73,82.35 200.05,82.02 200.05,81.72 199.7,81.36 v2(199.64,81.36)
  LAY3 w0.087: 189.9,83.31 186.81,83.31 186.27,83.85 176.48,83.85 175.35,82.72 172.86,82.72 168.44,78.3 154.01,78.3 146.91,71.2 134.6,71.2 130.94,67.54 97.95,67.54 89.45,59.05 89.45,50.63 87.07,48.24 87.07,47.49 87.29,47.28 87.56,47.28 87.65,47.37 87.65,47.82 87.76,47.94 87.91,47.94 88.11,47.75 v2(88.11,47.7)
PCIE_TX_DN_11_SSD: length 146.4
  TOP w0.076: C331.2 201.99,81.06 201.99,81.18 v2(202.21,81.41)
  TOP w0.109: CN5.35 86.04,44.67 85.87,44.5 85.11,44.5 v2(84.92,44.69)
  LAY3 w0.076: v2(202.21,81.41) 202.21,82.3 200.94,83.57 199.12,83.57 198.98,83.71 192.5,83.71 192.07,84.14 189.92,84.14 189.91,84.15 189.9,84.15
  LAY3 w0.087: v2(84.92,44.69) 85.02,44.59 86.07,44.59 86.22,44.73 86.22,49.16 87.87,50.81 87.87,59.24 97.91,69.27 131.46,69.27 134.24,72.06 146.55,72.06 156.55,82.05 170.5,82.05 172.29,83.84 175.25,83.84 176.11,84.7 187.39,84.7 187.94,84.15 189.9,84.15
PCIE_TX_DN_12_SSD: length 148.4
  TOP w0.076: U1.A25 201.29,77.45 202.17,78.33 202.65,78.33 202.72,78.41 202.72,78.65 202.82,78.75 v2(203.01,78.75)
  TOP w0.109: v2(91.41,41.57) 91.2,41.36 90.28,41.36 C333.2
  LAY3 w0.076: v2(203.01,78.75) 202.77,78.51 202.25,78.51 201.99,78.77 201.99,79.29 201.01,80.27 199.22,80.27 197.15,82.34 190.73,82.34 190.15,81.76 189.92,81.76 189.91,81.77 189.9,81.77
  LAY3 w0.087: v2(91.41,41.57) 91.57,41.41 92,41.41 92.11,41.52 92.11,45.2 90.72,46.59 90.72,57.36 97.99,64.63 105.77,64.63 106.33,65.18 130.76,65.18 135.34,69.76 147.52,69.76 152.74,74.98 164.91,74.98 165.87,74.02 173.41,74.02 175.09,75.71 175.09,78.18 176.1,79.19 176.1,79.19 177.26,80.34 187.01,80.34 188.44,81.77 189.9,81.77
PCIE_TX_DP<4>: length 118.7
  TOP w0.076: v2(197.67,84.77) 197.46,84.56 197.46,84.34 C12.2
  LAY6 w0.076: 189.9,83.09 189.91,83.09 189.92,83.1 190.04,83.1 190.45,82.69 195.96,82.69 197.29,84.01 197.29,84.44 197.62,84.77 v2(197.67,84.77)
  LAY6 w0.087: 189.9,83.09 186.96,83.09 185.53,84.51 177.16,84.51 175.65,83 172.06,83 171.21,83.85 169.56,83.85 169.33,83.62 163.45,83.62 163.07,84 156.76,84 153.61,80.85 148.6,80.85 148.02,80.27 145.7,80.27 144.48,79.05 137.45,79.05 137.01,79.5 131.64,79.5 130.12,81.02 126.38,81.02 124.12,78.76 123.75,78.76 v2(123.54,78.55)
  BOTTOM w0.109: v2(123.54,78.55) 123.72,78.74 124.14,78.74 125.43,77.45 125.43,46.77 125.43,46.17 125.2,45.95 U9.17
PCIE_TX_DP_1_WIFI: length 139.4
  TOP w0.076: C10.2 195.61,84.38 195.61,84.65 v2(195.42,84.84)
  TOP w0.109: CN26.35 125.17,21.86 125.31,22 127.26,22 129.55,24.29 129.55,30.65 132.87,33.98 132.87,44.55 130.78,46.65 130.78,49.33 v2(130.92,49.47)
  LAY6 w0.076: 189.9,84.02 189.91,84.02 189.92,84.01 189.97,84.01 189.97,84 190.07,84 190.56,83.51 194.79,83.51 195.52,84.24 195.52,84.74 v2(195.42,84.84)
  LAY6 w0.087: 189.9,84.02 187.51,84.02 185.68,85.85 177.31,85.85 175.3,83.83 172.67,83.83 171.26,85.24 168.13,85.24 167.75,84.86 166.31,84.86 166.03,85.14 156.01,85.14 152.58,81.71 144.94,81.71 143.55,80.32 140.31,80.32 139.53,81.09 136.78,81.09 136.06,81.81 133.08,81.81 132.61,81.34 131.79,81.34 v2(131.58,81.55)
  BOTTOM w0.109: v2(130.92,49.47) 130.92,50.82 130.59,51.15 130.59,74.42 132.99,76.82 132.99,80.77 132.24,81.52 131.61,81.52 v2(131.58,81.55)
PCIE_TX_DP_9_SSD: length 2.4
  TOP w0.109: C326.2 88.85,50.31 88.01,50.31 87.87,50.17 CN5.13
PCIE_TX_DP_10_SSD: length 138.7
  TOP w0.076: C330.2 200.16,80.85 200.16,81.3 v2(200.22,81.36)
  TOP w0.109: v2(88.11,47.09) 88.03,47.17 CN5.25
  LAY3 w0.076: v2(200.22,81.36) 200.22,82.09 199.79,82.51 198.74,82.51 198.01,83.24 192,83.24 191.76,83.48 189.92,83.48 189.91,83.49 189.9,83.49
  LAY3 w0.087: 189.9,83.49 186.89,83.49 186.35,84.03 176.4,84.03 175.28,82.91 172.78,82.91 168.36,78.49 153.93,78.49 146.83,71.38 134.52,71.38 130.87,67.72 97.87,67.72 89.27,59.12 89.27,50.7 86.89,48.32 86.89,47.42 87.21,47.09 v2(88.11,47.09)
PCIE_TX_DP_11_SSD: length 146.4
  TOP w0.076: C332.2 201.82,81.09 201.82,81.23 v2(201.64,81.41)
  TOP w0.109: v2(84.92,44.09) 85.11,44.28 85.87,44.28 85.99,44.17 CN5.37
  LAY3 w0.076: 189.9,83.97 189.91,83.97 189.92,83.98 192,83.98 192.43,83.55 198.91,83.55 199.05,83.41 200.87,83.41 202.05,82.23 202.05,81.76 201.7,81.41 v2(201.64,81.41)
  LAY3 w0.087: v2(84.92,44.09) 85.23,44.4 86.15,44.4 86.4,44.66 86.4,49.08 88.05,50.73 88.05,59.16 97.99,69.09 131.54,69.09 134.32,71.87 146.63,71.87 156.62,81.87 170.57,81.87 172.36,83.66 175.32,83.66 176.18,84.52 187.31,84.52 187.86,83.97 189.9,83.97
PCIE_TX_DP_12_SSD: length 148.4
  TOP w0.076: U1.B25 201.09,77.02 202.24,78.17 v2(203.01,78.17)
  TOP w0.109: C338.2 90.24,41.14 91.24,41.14 v2(91.41,40.97)
  LAY3 w0.076: 189.9,81.59 189.91,81.59 189.92,81.6 190.22,81.6 190.8,82.18 197.08,82.18 199.15,80.11 200.94,80.11 201.82,79.23 201.82,78.71 202.18,78.34 202.84,78.34 v2(203.01,78.17)
  LAY3 w0.087: v2(91.41,40.97) 91.67,41.23 92.08,41.23 92.3,41.45 92.3,45.27 90.9,46.67 90.9,57.28 98.06,64.44 105.85,64.44 106.41,65 130.84,65 135.41,69.57 147.59,69.57 152.81,74.79 164.84,74.79 165.79,73.84 173.49,73.84 175.28,75.63 175.28,78.11 176.17,79 176.18,79 177.33,80.16 187.08,80.16 188.51,81.59 189.9,81.59
PCIE_WAKE#: length 180.5
  TOP w0.076: 192.77,51.76 195.1,54.09 195.1,54.8 U1.BB15
  TOP w0.102: 192.77,51.76 191.52,50.52 v2(191.33,50.52) ; v2(133.37,48.65) 134.69,47.33 134.69,44.26 v2(134.12,43.68) ; v2(75.41,55.51) 75.43,55.53 75.43,56.5 R3128.1 ; R3126.1 120.58,28.68 118.81,30.45 118.81,43.28 118.61,43.48 118.61,46.91 v2(120.62,48.92)
  LAY3 w0.102: v2(66.6,62.68) 67.05,62.22 67.05,55.82 67.1,55.77 v2(67.1,55.47)
  LAY6 w0.076: v2(191.33,50.52) 190.68,49.87 189.54,49.87 188.24,48.57 186.96,48.57 184.36,45.97 176.96,45.97 176.13,45.14
  LAY6 w0.102: v2(75.41,55.51) 75.41,55.51 ; 75.41,55.51 67.14,55.51 v2(67.1,55.47) ; 75.41,55.51 75.75,55.18 84.42,55.18 85.12,54.48 91.85,54.48 92.58,53.75 96.39,53.75 97.61,52.54 114.25,52.54 118.14,48.65 120.35,48.65 v2(120.62,48.92) 121.06,48.47 125.42,48.47 125.96,47.93 132.64,47.93 v2(133.37,48.65) 139.4,48.65 146.49,41.56 163.07,41.56 165.88,44.37 170.79,44.37 171.57,45.14 176.13,45.14
  BOTTOM w0.102: v2(134.12,43.68) 134.09,43.66 R313.2 ; R416.2 v2(66.6,62.68) ; R18.2 190.79,50.22 191.04,50.22 v2(191.33,50.52)
PD#: length 5.4
  BOTTOM w0.102: U17.4 17.41,26.14 16.81,25.54 16.81,23.82 16.92,23.7 16.92,22.7 16.33,22.11 U16.47
PLT_RST_BUF*: length 175.8
  TOP w0.109: CN16.4 68.38,64.88 68.52,64.74 68.52,62.83 67.09,61.4 v2(66.17,61.4) ; U2.4 167.45,49.97 R13.1 167.45,48.75 167.9,49.2 169.73,49.2 170.03,48.89 170.03,43.23 v2(165.87,39.06) ; v2(75.46,52.84) 75.46,52.92 77.59,55.05 R200.1
  LAY3 w0.087: v2(66.97,53.07) 65.73,54.31 65.73,60.96 v2(66.17,61.4)
  LAY6 w0.087: v2(165.87,39.06) 164.18,39.06 163.51,39.73 142.54,39.73 136.01,46.26 v2(134.14,46.26) 134.04,46.36 131.06,46.36 130,45.31 124.88,45.31 122.99,47.2 115.52,47.2 111.82,50.91 110.1,50.91 109.26,50.07 93.99,50.07 91.99,52.07 89.71,52.07 89.48,51.84 76.46,51.84 v2(75.46,52.84) 67.2,52.84 v2(66.97,53.07)
  BOTTOM w0.109: R401.2 65.56,62.02 v2(66.17,61.4) ; R155.2 135.68,25.43 136.35,26.11 137.85,26.11 138.06,25.9 U18.1 138.46,25.3 138.79,25.62 138.79,28.65 141.76,31.62 141.76,39.28 136.86,44.18 136.86,44.9 136.3,45.46 135.36,45.46 134.96,45.86 U10.1 134.9,46.23 134.17,46.23 v2(134.14,46.26) 134.11,46.23 R317.2
PM_BATLOW#: length 146
  TOP w0.076: U1.AU13 193.88,57.94 v2(194.22,57.61)
  LAY3 w0.076: v2(194.22,57.61) 193.86,57.61 192.22,55.97 188.09,55.97
  LAY3 w0.102: v2(174.54,51.44) 176.29,51.44 177.51,52.66 180.16,52.66 183.3,55.8 187.92,55.8 188.09,55.97
  LAY6 w0.102: v2(67.61,58.57) 71.16,58.57 71.93,59.33 95.23,59.33 95.97,58.59 100.23,58.59 101.33,57.5 114.1,57.5 119.13,52.47 145.39,52.47 147.12,50.74 163.81,50.74 164.89,49.67 165.55,49.67 166.72,50.83 173.86,50.83 174.46,51.44 v2(174.54,51.44)
  BOTTOM w0.102: v2(174.54,51.44) 174.67,51.31 R11.2 ; v2(67.61,58.57) 67.61,62.8 67.16,63.24 64.44,63.24 63.86,62.66 U22.20
PM_CPUPWRGD: length 5.2
  TOP w0.076: TP5.1 228.52,77.52 227.94,78.1 226.04,78.1 U1.A68
PM_EC_PWRBTN#: length 172.1
  TOP w0.076: R24.2 190.95,50.35 v2(190.7,50.61)
  LAY3 w0.102: v2(49.26,54.52) 48.94,54.83 48.94,66.26 47.66,67.55 v2(47.66,70.59)
  LAY6 w0.076: 176.13,46.9 177.13,47.9 185.39,47.9 186.38,48.89 188.18,48.89 189.49,50.2 190.29,50.2 v2(190.7,50.61)
  LAY6 w0.102: 176.13,46.9 175,45.77 171.75,45.77 170.55,44.57 165.68,44.57 162.93,41.83 146.73,41.83 139.45,49.11 133.2,49.11 132.25,48.15 126.03,48.15 125.49,48.69 124.62,48.69 123.79,49.51 120.49,49.51 119.94,48.97 118.22,48.97 114.41,52.78 97.99,52.78 96.75,54.01 92.8,54.01 92.07,54.75 85.25,54.75 84.54,55.46 76.23,55.46 75.69,56 54.13,56 52.04,53.91 49.87,53.91 v2(49.26,54.52)
  BOTTOM w0.102: U22.97 47.92,70.86 v2(47.66,70.59)
PM_LANPHY_ENABLE: length 10.5
  TOP w0.076: 195.8,52.26 196.51,52.97 196.51,54.41 196.7,54.6 196.7,54.96 196.65,55.08 196.65,55.2 196.72,55.41 196.72,55.56 196.66,55.72 196.66,55.8 196.44,56.5 196.44,56.5 196.27,56.68 U1.AW17
  TOP w0.102: 195.8,52.26 195.8,51.51 193.67,49.39 193.67,48.59 TP14.1
PM_RSMRST#: length 182.6
  TOP w0.076: U1.AY17 196.27,55.97 196.37,55.86 196.47,55.74 196.54,55.54 196.54,55.42 196.48,55.19 196.48,55.05 196.53,54.93 196.53,54.67 196.34,54.48 196.34,53.21 195.46,52.33 195.46,51.54 194.42,50.5 v2(194.14,50.5)
  LAY3 w0.102: v2(53.61,70.61) 53.61,53.97 v2(53.95,53.63)
  LAY6 w0.102: v2(180.02,41.17) 175.41,41.17 174.97,41.6 166.65,41.6 165.23,40.18 146.6,40.18 139.72,47.06 131.04,47.06 130.35,46.36 125.56,46.36 124.2,47.72 117.38,47.72 113.54,51.56 97.35,51.56 96.54,50.74 94.01,50.74 91.13,53.63 85.48,53.63 84.51,52.66 78.48,52.66 76.93,54.21 54.54,54.21 v2(53.95,53.63)
  BOTTOM w0.076: R26.1 194.14,50.51 v2(194.14,50.5) 194.14,49.92 193.49,49.27 193.49,44.56 ; 53.71,70.7 v2(53.61,70.61)
  BOTTOM w0.102: 193.49,44.56 193.49,43.39 191.27,41.17 v2(180.02,41.17) ; U22.112 53.92,70.92 53.71,70.7
PM_SLP_S0*: length 163.6
  TOP w0.076: U1.AT11 193.19,58.24 v2(193.3,58.24)
  TOP w0.102: R662.1 170.37,53.18 169.72,52.52 v2(169.39,52.52)
  LAY6 w0.203: v2(52.81,59.48) 53.68,58.62 64.42,58.62 64.95,59.15 67.75,59.15 67.9,59 71.14,59 71.77,59.63 95.4,59.63 96.12,58.91 100.73,58.91 101.85,57.79 114.24,57.79 119.25,52.79 145.53,52.79 147.02,51.3 162.4,51.3 163.67,52.57 169.33,52.57 v2(169.39,52.52) 170.57,51.34 171.98,51.34 172.81,52.18 177.82,52.18 178.34,52.69 181.95,52.69 v2(182.04,52.59) 182.22,52.59 184.5,54.87 185.04,54.87 185.49,55.33 191.04,55.33 193.3,57.59 v2(193.3,58.24)
  BOTTOM w0.203: U22.108 52.32,69.93 52.81,69.44 v2(52.81,59.48)
PM_SLP_S3*: length 410.4
  TOP w0.076: U1.AP15 v2(195.13,59.51)
  TOP w0.102: v2(168.28,80.32) 169.36,81.4 R828.1
  TOP w0.203: U6.2 170.36,54.95 v2(170.38,54.96)
  LAY3 w0.203: v2(183.42,12.29) 181.11,14.59 180.15,14.59 179.85,14.89 179.85,17.32 178.99,18.18 175.33,18.18 173.36,20.15 173.36,29.95 172.66,30.65 172.66,40.76 173.79,41.89 173.79,49.6 174.68,50.49 v2(176.09,50.49) ; 194.69,57.34 194.69,59.07 v2(195.13,59.51) ; v2(155.78,61.36) v2(155.78,67.37) ; v2(187.05,11.62) 187.29,11.37 193.12,11.37 193.6,10.89 239.6,10.89 242.89,14.18 242.89,24.56 230.22,37.23 230.22,41.87 233.74,45.39 v2(235.36,45.39)
  LAY3 w0.254: v2(155.78,61.36) 155.78,59.55 150.44,54.2 v2(150.44,53.82) 151.88,52.37 v2(151.88,50.2)
  LAY3 w0.305: 194.69,57.34 194.47,57.12 193.91,57.12 192.41,55.62 188.38,55.62 187.95,55.19 185.81,55.19 185.21,54.59 182.81,54.59 180.52,52.31 179.65,52.31 177.83,50.49 v2(176.09,50.49)
  LAY6 w0.152: v2(176.09,50.49) 169.46,50.49
  LAY6 w0.203: 169.46,50.49 166.9,50.49 165.77,49.36 164.52,49.36 163.48,50.4 152.06,50.4 151.88,50.22 v2(151.88,50.2) ; v2(187.05,11.62) 184.09,11.62 v2(183.42,12.29) ; v2(170.38,54.96) 169.84,54.43 158.74,54.43 158.18,54.99 156.25,54.99 155.09,53.82 v2(150.44,53.82) 146.75,53.82 146.35,54.22 124.45,54.22 124.07,53.84 120.19,53.84 119.94,54.08 119.11,54.08 114.67,58.52 102.71,58.52 101.53,59.7 96.55,59.7 95.85,60.4 70.3,60.4 69.98,60.08 64.81,60.08 63.68,61.21 55.53,61.21 54.56,60.24 v2(47.81,60.24) 46.14,60.24 45.38,59.48 40.68,59.48 40.28,59.08 37.56,59.08 32.61,64.03 v2(29.61,64.03)
  BOTTOM w0.152: v2(47.81,60.24) 47.42,59.86 U22.70
  BOTTOM w0.203: U59.3 156.16,60.98 v2(155.78,61.36) ; v2(155.78,67.37) 156.4,67.99 158.97,67.99 161.97,70.99 161.97,72.34 164.82,75.18 164.82,75.86 168.28,79.32 v2(168.28,80.32) ; R550.2 236.76,43.99 v2(235.36,45.39)
  BOTTOM w0.305: Q65.1 29.59,75.29 30.03,75.29 31.35,73.97 31.35,69.52 29.21,67.37 R808.1 29.21,66.29 29.61,65.88 v2(29.61,64.03)
PM_SLP_S4*: length 377.5
  TOP w0.076: U1.BA16 195.67,55.77 195.67,53.8 195.6,53.74
  TOP w0.102: R827.1 169.95,80.74 169.27,80.74 v2(168.85,80.32) ; v2(191.85,48.78) 192.22,49.14 192.22,49.7 192.11,49.82 192.11,50.24 195.6,53.74
  LAY3 w0.203: v2(158.34,67.51) 159.8,67.51 165,62.3 165,56.1 166.32,54.78 166.32,43.02 v2(166.86,42.49) ; v2(171.8,44.13) 172.28,43.65 172.28,43.15 171.95,42.82 171.95,30.34 171.54,29.93 171.54,20.98 175.11,17.41 176.83,17.41 178.66,15.58 178.66,14.71 179.47,13.9 180.61,13.9 183.04,11.46 185.7,11.46 187.19,12.95 193.01,12.95 194.43,11.53 239.25,11.53 242.22,14.5 242.22,23.25 229.53,35.94 229.53,45.02 231.42,46.91 240.33,46.91 v2(241.13,46.11) ; v2(191.85,48.78) 191.39,48.32 191.39,46.34 187.81,42.76 181.69,42.76 180.34,44.11 v2(176.47,44.11)
  LAY6 w0.203: v2(48.71,53.34) 48.77,53.27 52.77,53.27 54.07,54.57 77.28,54.57 78.92,52.93 84.19,52.93 85.15,53.88 91.47,53.88 92.18,53.18 96.11,53.18 97.35,51.94 113.68,51.94 117.65,47.98 124.35,47.98 125.68,46.64 130.24,46.64 130.94,47.34 139.83,47.34 146.63,40.55 162.86,40.55 164.8,42.49 v2(166.86,42.49) 170.08,42.49 171.72,44.13 v2(171.8,44.13) 176.45,44.13 v2(176.47,44.11)
  BOTTOM w0.102: Q62.1 v2(241.13,46.11) 240.44,45.42 240.44,43.67 239.88,43.11 R552.1
  BOTTOM w0.203: U22.69 47.84,59.46 48.16,59.14 48.16,58.11 47.83,57.77 47.83,57.75 47.34,57.26 47.34,54.71 v2(48.71,53.34) ; v2(158.34,67.51) 159.02,67.51 162.35,70.84 162.35,72.18 165.19,75.03 165.19,75.7 168.85,79.35 v2(168.85,80.32)
PM_SLP_SUS*: length 181.9
  TOP w0.102: R616.2 180.82,50.62 v2(180.64,50.8)
  LAY6 w0.102: v2(18.71,58.09) 18.73,58.07 23.61,58.07 29.01,63.47 32.54,63.47 39.24,56.78 40.95,56.78 42.4,55.33 v2(51.12,55.33) 52.32,56.52 60.23,56.52 60.88,57.17 61.56,57.17 61.84,56.89 65.64,56.89 66.12,57.37 71.35,57.37 72.42,58.44 92.07,58.44 93.06,57.45 97.97,57.45 98.87,56.55 113.63,56.55 118.57,51.61 143.34,51.61 146.49,48.46 155.2,48.46 156.44,49.7 163.48,49.7 164.17,49.02 167.79,49.02 168.81,50.05 174.92,50.05 175.32,49.65 178.96,49.65 180.1,50.8 v2(180.64,50.8)
  BOTTOM w0.152: R71.2 18.71,60.54 v2(18.71,58.09) ; U22.56 v2(51.12,55.33)
  BOTTOM w0.305: R71.2 17.74,61.52 Q4.1
PM_SUS_STAT*: length 158.6
  TOP w0.076: U1.BA11 192.92,55.21 192.92,54.27 191.74,53.09 190.29,53.09 189.43,52.23 188.4,52.23 187.91,51.75 187.91,49.16 184.38,45.62
  TOP w0.102: 182.02,36.18 183.24,37.4 183.24,44.49 184.38,45.62
  TOP w0.109: v2(114.15,62.43) 116.52,62.43 117.45,61.49 127.42,61.49 145.09,43.83 145.09,40.78 153.3,32.57 167.64,32.57 169.3,34.23 180.07,34.23 182.02,36.18
  LAY6 w0.087: v2(114.15,62.43) 113.85,62.73 77.88,62.73 77.06,63.56 67.09,63.56 v2(66.87,63.78)
  BOTTOM w0.109: v2(66.87,63.78) 66.74,63.78 66.57,63.95 R488.1
